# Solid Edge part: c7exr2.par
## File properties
Author: CADCIM
Template: Iso Part.par
Last saved by: CADCIM
Revision: 7
Application: Solid Edge
Accuracy: 0.990
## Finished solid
Body 1: solid body, 20 faces, 54 edges, 36 vertices.
  Faces by surface: plane 13, cylinder 7
  Edges by curve: line 40, circle 14
Bounding box of the edges (mm): 174.376 x 50.000 x 89.138, from (-48, -25, 0) to (126.3762, 25, 89.1384).
Cylindrical faces by radius (mm): R5 x2, R6 x2, R15 x2, R26.3762 x1
Planar faces by outward normal: +y 3, +z 1, -y 3, -z 1, oblique 5
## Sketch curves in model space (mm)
line (-35.0071, -31.9355, 60.6341) -> (-35.0033, -25, 60.6275)
line (-55.4253, -31.9355, 95.9994) -> (-35.0071, -31.9355, 60.6341)
line (-55.4253, 29.2698, 95.9994) -> (-55.4253, -31.9355, 95.9994)
line (-45, 29.2698, 77.9423) -> (-55.4253, 29.2698, 95.9994)
line (-45, 25, 77.9423) -> (-45, 29.2698, 77.9423)
arc centre (-45, 19, 77.9423) radius 6 from (-45, 25, 77.9423) through (-47.6127, 21.9489, 82.4675) to (-47.6548, 16.2055, 82.5405)
line (-47.6548, 16.2055, 82.5405) -> (-37.6548, -21.7945, 65.2199)
line (101.8846, 0, 12) -> (99.9982, 0, 12)
line (-52.8954, 0, 91.6175) -> (-53, 0, 91.7987)
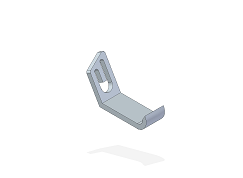
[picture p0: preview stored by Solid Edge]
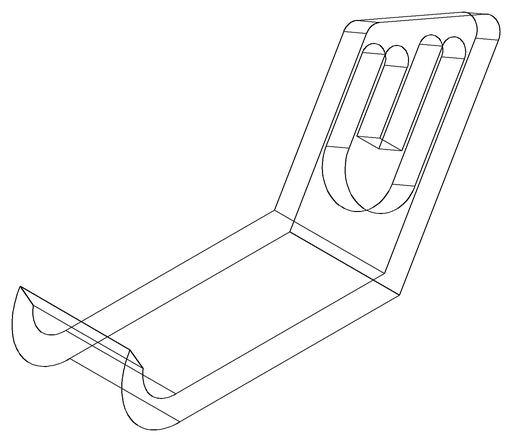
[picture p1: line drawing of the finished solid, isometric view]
